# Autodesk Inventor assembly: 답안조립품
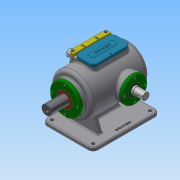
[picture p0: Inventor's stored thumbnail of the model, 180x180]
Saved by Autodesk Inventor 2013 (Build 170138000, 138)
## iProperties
Created: 2018-08
Part Number: 답안조립품
Document SubType Name: Assembly
Designer: user
Author: user
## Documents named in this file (15)
- C:\Users\user\Desktop\380808V1014\380808V1014\공용부품_20180825_1\답안조립품.iam
- C:\Users\user\Desktop\380808V1014\380808V1014\공용부품_20180825_1\본체.ipt
- C:\Users\user\Desktop\380808V1014\380808V1014\공용부품_20180825_1\고정플레이트.ipt
- C:\Users\user\Desktop\380808V1014\380808V1014\공용부품_20180825_1\베어링 6205.ipt
- 베어링 6205.ipt
- C:\Users\user\Desktop\380808V1014\380808V1014\공용부품_20180825_1\볼트 M4x0.7.ipt
- C:\Users\user\Desktop\380808V1014\380808V1014\공용부품_20180825_1\부시.ipt
- C:\Users\user\Desktop\380808V1014\380808V1014\공용부품_20180825_1\상부커버.ipt
- C:\Users\user\Desktop\380808V1014\380808V1014\공용부품_20180825_1\슬라이드 커버.ipt
- C:\Users\user\Desktop\380808V1014\380808V1014\공용부품_20180825_1\슬라이드.ipt
- C:\Users\user\Desktop\380808V1014\380808V1014\공용부품_20180825_1\오일 실 25 38 8.ipt
- C:\Users\user\Desktop\380808V1014\380808V1014\공용부품_20180825_1\육각머리볼트 M4.ipt
- C:\Users\user\Desktop\380808V1014\380808V1014\공용부품_20180825_1\축 커버.ipt
- C:\Users\user\Desktop\380808V1014\380808V1014\공용부품_20180825_1\편심축.ipt
- C:\Users\user\Desktop\380808V1014\380808V1014\공용부품_20180825_1\가변스프링.ipt
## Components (14 placed, 3 different names)
1. 고정플레이트:1 — 플러쉬:44
2. 가변스프링:1
3. M4x0.7:1
4. M4x0.7:4
5. M4x0.7:5
6. M4x0.7:6
7. M4x0.7:2
8. M4x0.7:7
9. M4x0.7:8
10. M4x0.7:9
11. M4x0.7:3
12. M4x0.7:10
13. M4x0.7:11
14. M4x0.7:12
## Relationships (1: Flush 1)
- 플러쉬:44 [Flush]: 고정플레이트:1
